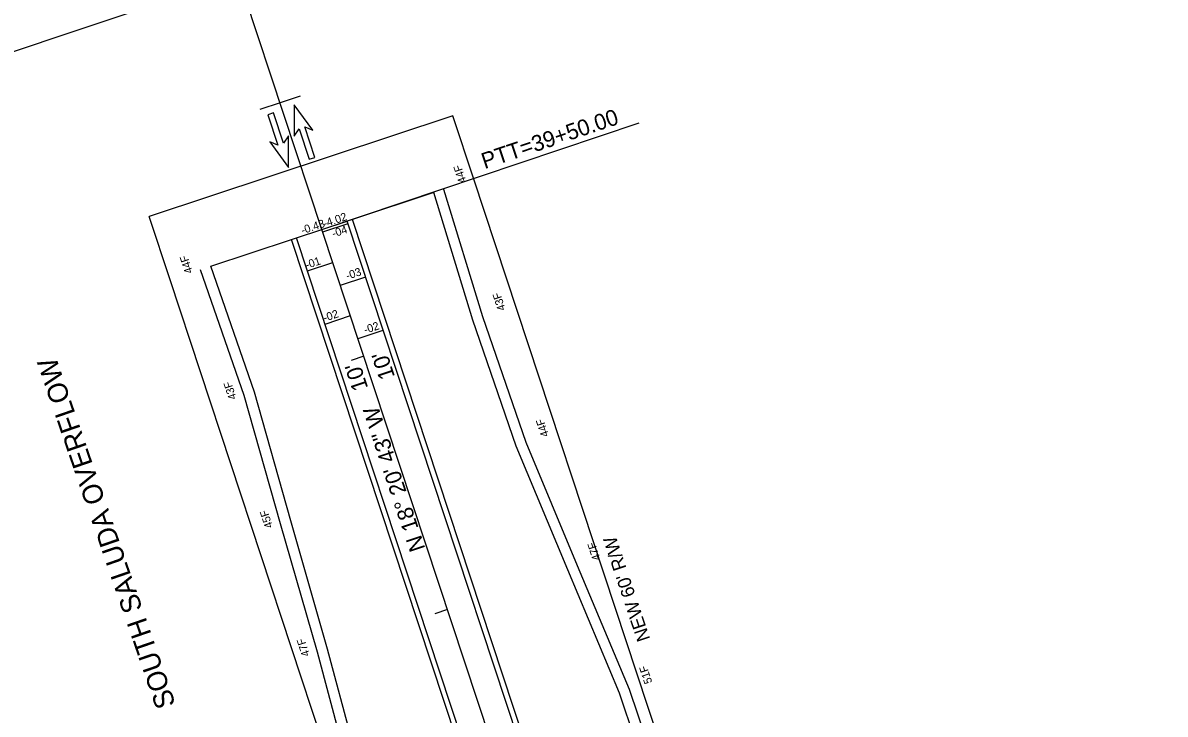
# Model space of a CAD drawing. Extents: x 1528853 to 1624411, y 1119753 to 1162242.
# Drawn here: x 1529293.8 to 1529722.2, y 1160821.6 to 1161080.6 of the extents above; entities that cross this region are included whole.
import ezdxf

# ---------------------------------------------------------------- set-up
doc = ezdxf.new("R2010")
doc.units = 0
for name, color, linetype in [('RD_HC_Cl', 7, 'Continuous'), ('RD_HC_Data', 7, 'Continuous'), ('RD_HC_Data_Tic', 7, 'Continuous'), ('RD_PD_ALT1_TX', 7, 'Continuous'), ('RD_PD_CstnLmt', 7, 'Continuous'), ('RD_PD_CstnLmt_TX', 7, 'Continuous'), ('RD_PD_DR_ErosCtrl', 7, 'Continuous'), ('RD_PD_Final_TrvlWay', 7, 'Continuous'), ('RD_PD_Final_TX', 7, 'Continuous'), ('RD_PD_PaveShd', 7, 'Continuous'), ('RD_PD_RW', 7, 'Continuous'), ('RD_SHT_ShtClip', 7, 'Continuous'), ('RD_TX_Pipe_ElevEX', 7, 'Continuous')]:
    doc.layers.add(name, color=color, linetype=linetype)

msp = doc.modelspace()

# ---------------------------------------------------------------- linework, layer by layer
at = {"layer": 'RD_HC_Cl'}
for p, q in [((1529406.02, 1161003.2), (1529346.24, 1161183.48)), ((1529500.12, 1160718.34), (1529406.02, 1161003.2))]:
    msp.add_line(p, q, dxfattribs=at)
at = {"layer": 'RD_HC_Data'}
msp.add_line((1529406.02, 1161003.2), (1529524.92, 1161043.14), dxfattribs=at)
at = {"layer": 'RD_HC_Data_Tic'}
for p, q in [((1529397.87, 1161053.18), (1529390.28, 1161050.66)), ((1529390.28, 1161050.66), (1529382.68, 1161048.14)), ((1529421.7, 1160955.72), (1529416.95, 1160954.16)), ((1529453.07, 1160860.77), (1529448.32, 1160859.2))]:
    msp.add_line(p, q, dxfattribs=at)
at = {"layer": 'RD_PD_ALT1_TX'}
for p, q in [((1529406.33, 1161002.25), (1529415.82, 1161005.4)), ((1529400.6, 1160987.71), (1529410.11, 1160990.86)), ((1529412.94, 1160982.32), (1529422.41, 1160985.46)), ((1529407.19, 1160967.77), (1529416.72, 1160970.93)), ((1529419.55, 1160962.39), (1529428.99, 1160965.52))]:
    msp.add_line(p, q, dxfattribs=at)
at = {"layer": 'RD_PD_CstnLmt'}
for p, q in [((1529447.9, 1161017.04), (1529417.41, 1161006.96)), ((1529462.57, 1160969.23), (1529447.9, 1161017.04)), ((1529364.28, 1160989.41), (1529394.62, 1160999.44)), ((1529380.7, 1160942.18), (1529364.28, 1160989.41)), ((1529478.82, 1160921.94), (1529462.57, 1160969.23)), ((1529394.3, 1160894.01), (1529380.7, 1160942.18)), ((1529498.15, 1160875.67), (1529478.82, 1160921.94)), ((1529408.14, 1160845.93), (1529394.3, 1160894.01)), ((1529517.58, 1160829.42), (1529498.15, 1160875.67)), ((1529421.11, 1160797.56), (1529408.14, 1160845.93)), ((1529533.7, 1160782.09), (1529517.58, 1160829.42))]:
    msp.add_line(p, q, dxfattribs=at)
at = {"layer": 'RD_PD_DR_ErosCtrl'}
for p, q in [((1529466.38, 1160970.46), (1529451.73, 1161018.21)), ((1529376.88, 1160940.98), (1529360.5, 1160988.1)), ((1529482.56, 1160923.36), (1529466.38, 1160970.46)), ((1529390.45, 1160892.92), (1529376.88, 1160940.98)), ((1529501.84, 1160877.21), (1529482.56, 1160923.36)), ((1529404.28, 1160844.86), (1529390.45, 1160892.92)), ((1529521.32, 1160830.85), (1529501.84, 1160877.21)), ((1529417.25, 1160796.52), (1529404.28, 1160844.86)), ((1529537.49, 1160783.38), (1529521.32, 1160830.85))]:
    msp.add_line(p, q, dxfattribs=at)
at = {"layer": 'RD_PD_Final_TrvlWay'}
for p, q in [((1529396.52, 1161000.05), (1529415.51, 1161006.35)), ((1529509.61, 1160721.48), (1529415.51, 1161006.34)), ((1529490.62, 1160715.2), (1529396.52, 1161000.06))]:
    msp.add_line(p, q, dxfattribs=at)
at = {"layer": 'RD_PD_Final_TX'}
for p, q in [((1529402.63, 1161040.42), (1529395.61, 1161049.95)), ((1529395.61, 1161049.95), (1529395.65, 1161038.11)), ((1529387.88, 1161046.89), (1529385.74, 1161046.18)), ((1529385.74, 1161046.18), (1529389.51, 1161034.79)), ((1529391.64, 1161035.49), (1529387.88, 1161046.89)), ((1529395.65, 1161038.11), (1529397.41, 1161040.91)), ((1529397.41, 1161040.91), (1529401.18, 1161029.51)), ((1529403.31, 1161030.22), (1529399.55, 1161041.61)), ((1529399.55, 1161041.61), (1529402.63, 1161040.42)), ((1529386.43, 1161035.98), (1529393.45, 1161026.45)), ((1529389.51, 1161034.79), (1529386.43, 1161035.98)), ((1529393.41, 1161038.29), (1529391.64, 1161035.49)), ((1529393.45, 1161026.45), (1529393.41, 1161038.29)), ((1529401.18, 1161029.51), (1529403.31, 1161030.22))]:
    msp.add_line(p, q, dxfattribs=at)
at = {"layer": 'RD_PD_PaveShd'}
for p, q in [((1529417.4, 1161006.98), (1529415.51, 1161006.35)), ((1529509.38, 1160728.57), (1529417.41, 1161006.96)), ((1529394.62, 1160999.42), (1529396.52, 1161000.05)), ((1529486.53, 1160721.21), (1529394.62, 1160999.44))]:
    msp.add_line(p, q, dxfattribs=at)
at = {"layer": 'RD_PD_RW'}
for p, q in [((1529455.1, 1161045.81), (1529341.2, 1161008.04)), ((1529462.97, 1161022.08), (1529455.1, 1161045.81)), ((1529549.25, 1160760.9), (1529462.99, 1161022.02)), ((1529349.06, 1160984.32), (1529341.2, 1161008.04)), ((1529435.3, 1160723.26), (1529349.04, 1160984.38))]:
    msp.add_line(p, q, dxfattribs=at)
at = {"layer": 'RD_SHT_ShtClip'}
msp.add_line((1528852.95, 1160923.06), (1529895.79, 1161273.06), dxfattribs=at)

# ---------------------------------------------------------------- texts
at = {"layer": 'RD_HC_Data'}
for s, height, rotation, p in [('PTT=39+50.00', 6, 18.568, (1529466.99, 1161025.79)), ('SOUTH SALUDA OVERFLOW', 7.5, 109.0239, (1529351.21, 1160825.2)), ('N 18%%d 20\' 43" W', 6, 108.3453, (1529444.84, 1160883.64))]:
    msp.add_text(s, height=height, rotation=rotation, dxfattribs=at).set_placement(p)
at = {"layer": 'RD_PD_ALT1_TX'}
for s, rotation, p in [('-04', 18.3453, (1529410.31, 1161000.14)), ('-01', 18.3453, (1529400.31, 1160988.38)), ('-03', 18.3453, (1529415.54, 1160984.32)), ('-02', 18.5527, (1529407.03, 1160968.56)), ('-02', 18.3453, (1529422.26, 1160964.07))]:
    msp.add_text(s, height=3, rotation=rotation, dxfattribs=at).set_placement(p)
at = {"layer": 'RD_PD_CstnLmt_TX'}
for s, p in [('44F', (1529460.25, 1161021.12)), ('44F', (1529357.63, 1160987.22)), ('43F', (1529474.92, 1160973.3)), ('43F', (1529374.05, 1160939.98)), ('44F', (1529491.17, 1160926.01)), ('45F', (1529387.65, 1160891.82)), ('47F', (1529510.5, 1160879.74)), ('47F', (1529401.49, 1160843.73)), ('51F', (1529529.92, 1160833.5))]:
    msp.add_text(s, height=3, rotation=108.2806, dxfattribs=at).set_placement(p)
at = {"layer": 'RD_PD_Final_TX'}
for p in [(1529433.44, 1160948.07), (1529423.39, 1160943.85)]:
    msp.add_text("10'", height=6, rotation=108.2813, dxfattribs=at).set_placement(p)
at = {"layer": 'RD_PD_RW'}
msp.add_text("NEW 60' R/W", height=5, rotation=108.5527, dxfattribs=at).set_placement((1529529.17, 1160849.78))
at = {"layer": 'RD_TX_Pipe_ElevEX'}
for s, p in [('-4.02', (1529407, 1161003.91)), ('-0.43', (1529398.69, 1161001.35))]:
    msp.add_text(s, height=3, rotation=18.3453, dxfattribs=at).set_placement(p)

doc.saveas('drawing.dxf')
